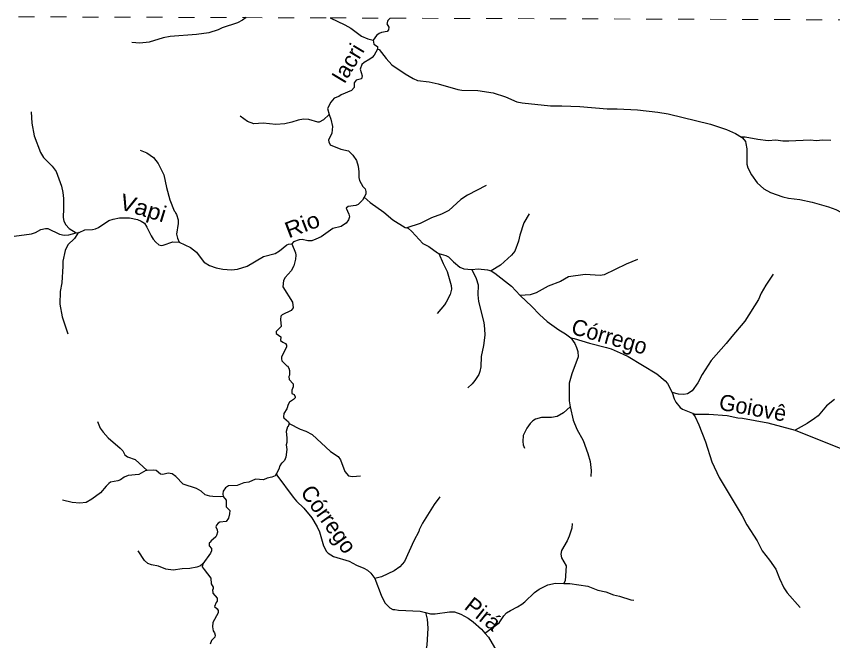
# Model space of a CAD drawing. Extents: x 551.6 to 577.6, y 7567 to 7594.7.
# Drawn here: x 558.55 to 563.65, y 7590.81 to 7594.71 of the extents above; entities that cross this region are included whole.
import ezdxf
from ezdxf.enums import TextEntityAlignment as Align

# ---------------------------------------------------------------- set-up
doc = ezdxf.new("R2010")
doc.units = 0
doc.header["$LTSCALE"] = 0.04
doc.linetypes.add('SHORT_DASHED', pattern=[2.7, 1.5, -1.2])
doc.layers.add('53', color=7, linetype='SHORT_DASHED', lineweight=13)
doc.layers.add('7', color=7, linetype='Continuous', lineweight=25)
doc.layers.add('61', color=7, linetype='Continuous')

msp = doc.modelspace()

# ---------------------------------------------------------------- linework, layer by layer
at = {"layer": '53'}
msp.add_lwpolyline([(557.7663, 7594.7075), (559.9893, 7594.6994), (560.513, 7594.6975), (560.888, 7594.6961), (564.4189, 7594.6832), (564.8007, 7594.6818), (567.5244, 7594.6698), (567.5959, 7594.6695), (570.5848, 7594.6561)], dxfattribs=at)
at = {"layer": '7'}
for points in [[(559.9893, 7594.6994), (559.9657, 7594.6833), (559.9335, 7594.6672), (559.8377, 7594.635), (559.8127, 7594.623), (559.7548, 7594.6053), (559.6791, 7594.594), (559.5134, 7594.5811), (559.4699, 7594.5739), (559.3814, 7594.5465), (559.3234, 7594.5401), (559.2743, 7594.5449)], [(560.513, 7594.6975), (560.6055, 7594.6552), (560.6433, 7594.6326), (560.7093, 7594.5843), (560.7479, 7594.5666), (560.7818, 7594.5593)], [(560.888, 7594.6961), (560.8734, 7594.6809), (560.8678, 7594.6616), (560.8799, 7594.6407), (560.8775, 7594.623), (560.8702, 7594.6133), (560.8332, 7594.606), (560.8187, 7594.5996), (560.8026, 7594.5875), (560.7818, 7594.5593)], [(560.7818, 7594.5593), (560.7865, 7594.5336), (560.8086, 7594.5186), (560.8101, 7594.503)], [(560.8101, 7594.503), (560.7881, 7594.4644), (560.7761, 7594.4507), (560.7616, 7594.4395), (560.7254, 7594.4201), (560.7109, 7594.4057), (560.7012, 7594.3783), (560.7133, 7594.3349), (560.7093, 7594.3171), (560.6762, 7594.3091), (560.6642, 7594.2914), (560.6642, 7594.264), (560.6473, 7594.2439), (560.5829, 7594.2181), (560.5676, 7594.2077), (560.5379, 7594.1956), (560.5177, 7594.1723), (560.4968, 7594.132), (560.5069, 7594.0954)], [(560.8101, 7594.503), (560.82, 7594.501), (560.863, 7594.4435), (560.8984, 7594.4049), (560.9813, 7594.3485), (561.0328, 7594.3187), (561.0586, 7594.3075), (561.131, 7594.2978), (561.1873, 7594.2866), (561.3113, 7594.2495), (561.337, 7594.2463), (561.4352, 7594.2447), (561.5318, 7594.2302), (561.6091, 7594.2045), (561.6799, 7594.1739), (561.7137, 7594.1666), (561.8891, 7594.1481), (561.9616, 7594.1489)], [(561.9616, 7594.1489), (562.0742, 7594.1449), (562.2432, 7594.1288), (562.306, 7594.1296), (562.4332, 7594.124), (562.5603, 7594.1095), (562.6247, 7594.0982), (562.8903, 7594.0338), (562.9901, 7594), (563.0464, 7593.9751), (563.0825, 7593.9534)], [(558.6442, 7594.1119), (558.6482, 7594.0403), (558.6635, 7593.9614), (558.7037, 7593.8568), (558.7214, 7593.8262), (558.7753, 7593.7715), (558.8019, 7593.7377), (558.8341, 7593.6476), (558.8429, 7593.6081), (558.8462, 7593.5703), (558.8478, 7593.5075), (558.8454, 7593.4512), (558.8502, 7593.4287), (558.8614, 7593.4061), (558.8816, 7593.3828), (558.9267, 7593.3549)], [(560.5069, 7594.0954), (560.4727, 7594.0612), (560.4453, 7594.0459), (560.4357, 7594.0459), (560.3793, 7594.0628), (560.3471, 7594.0652), (560.3133, 7594.0596), (560.2731, 7594.0459), (560.2296, 7594.0371), (560.1733, 7594.0322), (560.0944, 7594.0395), (560.0365, 7594.0363), (559.9978, 7594.0499), (559.9504, 7594.0838)], [(560.5069, 7594.0954), (560.5177, 7594.0644), (560.5274, 7594.0186), (560.5233, 7593.9783), (560.5032, 7593.9341), (560.504, 7593.9228), (560.5137, 7593.9051), (560.5805, 7593.8785), (560.6288, 7593.8672), (560.6553, 7593.8407), (560.6779, 7593.8069)], [(563.0825, 7593.9534), (563.0907, 7593.9485), (563.1076, 7593.9258), (563.1116, 7593.9131)], [(563.6412, 7593.9317), (563.5889, 7593.9333), (563.5518, 7593.9308), (563.5116, 7593.9333), (563.3796, 7593.9284), (563.341, 7593.9284), (563.2975, 7593.9333), (563.2492, 7593.9308), (563.1849, 7593.9389), (563.106, 7593.9534), (563.0825, 7593.9534)], [(563.1116, 7593.9131), (563.1172, 7593.8793), (563.1172, 7593.7844), (563.1221, 7593.7618), (563.1454, 7593.7176), (563.1824, 7593.6669), (563.2227, 7593.6298), (563.2637, 7593.6073), (563.3426, 7593.5799), (563.3764, 7593.5719), (563.4472, 7593.5638), (563.5261, 7593.5477), (563.6275, 7593.518), (563.6726, 7593.5003), (563.708, 7593.4818), (563.7192, 7593.4713), (563.7619, 7593.4134)], [(559.3258, 7593.8713), (559.3685, 7593.8552), (559.4087, 7593.8262), (559.4393, 7593.7876), (559.4731, 7593.7184), (559.4908, 7593.6379), (559.5125, 7593.5606), (559.5391, 7593.4922), (559.5455, 7593.4874), (559.5487, 7593.4753), (559.5536, 7593.4705), (559.5632, 7593.4367), (559.564, 7593.4142), (559.5536, 7593.3466), (559.5584, 7593.3224), (559.5693, 7593.2961)], [(560.6779, 7593.8069), (560.6883, 7593.7715), (560.6932, 7593.7361), (560.6932, 7593.7007), (560.6972, 7593.683), (560.7173, 7593.6451), (560.7318, 7593.6299), (560.7366, 7593.6138), (560.7366, 7593.5961), (560.7261, 7593.5775)], [(561.4875, 7593.6516), (561.3708, 7593.5896), (561.3298, 7593.563), (561.2549, 7593.4938), (561.2099, 7593.4721), (561.1471, 7593.4496), (561.0747, 7593.4141), (560.9925, 7593.3862)], [(560.7261, 7593.5775), (560.7157, 7593.559), (560.6892, 7593.5316), (560.6739, 7593.5252), (560.6248, 7593.5204), (560.6143, 7593.5099), (560.6304, 7593.4721), (560.6336, 7593.4544), (560.6288, 7593.4367), (560.6127, 7593.4165), (560.5974, 7593.4045), (560.5821, 7593.3956), (560.5306, 7593.3819), (560.4566, 7593.3312), (560.4244, 7593.3151), (560.3978, 7593.3055), (560.3729, 7593.3047), (560.3375, 7593.3127), (560.3189, 7593.3117), (560.2842, 7593.2987), (560.2738, 7593.2868)], [(560.7261, 7593.5775), (560.7624, 7593.5453), (560.8485, 7593.4842), (560.9057, 7593.4375), (560.9829, 7593.3892), (560.9925, 7593.3862)], [(558.9452, 7593.3578), (558.9806, 7593.3739), (559.0273, 7593.3755), (559.0466, 7593.3803), (559.0651, 7593.3892), (559.1303, 7593.4319), (559.1576, 7593.4415), (559.1979, 7593.4496), (559.259, 7593.4496), (559.3089, 7593.4383), (559.3331, 7593.4286), (559.3524, 7593.4158), (559.3677, 7593.3916)], [(561.7563, 7593.4745), (561.7225, 7593.4174), (561.6976, 7593.3417), (561.6895, 7593.3031), (561.6662, 7593.2411), (561.6461, 7593.2154), (561.5777, 7593.1542), (561.5195, 7593.1171)], [(558.5379, 7593.3353), (558.6474, 7593.3498), (558.6715, 7593.3578), (558.7053, 7593.3755), (558.7343, 7593.382), (558.7496, 7593.382), (558.8228, 7593.3465), (558.8518, 7593.3417), (558.8808, 7593.3433), (558.9267, 7593.3549), (558.9452, 7593.3578)], [(559.3677, 7593.3916), (559.3942, 7593.3369), (559.4079, 7593.316), (559.4232, 7593.2967), (559.4425, 7593.2814), (559.4602, 7593.2765), (559.4699, 7593.2773), (559.5311, 7593.2999), (559.5693, 7593.2961)], [(560.9925, 7593.3862), (561.0006, 7593.3836), (561.0239, 7593.3643), (561.0924, 7593.2894), (561.1294, 7593.2701), (561.1833, 7593.2298), (561.1918, 7593.2272)], [(558.9452, 7593.3578), (558.9355, 7593.349), (558.9162, 7593.3208), (558.8751, 7593.2814), (558.8582, 7593.2452), (558.8421, 7593.1792), (558.8429, 7593.147), (558.8357, 7593.044), (558.826, 7592.9892), (558.8252, 7592.9104), (558.8381, 7592.8315), (558.8743, 7592.7245)], [(559.5693, 7593.2961), (559.6405, 7593.2628), (559.659, 7593.2492), (559.6775, 7593.2339), (559.725, 7593.1695), (559.7323, 7593.1679), (559.7588, 7593.151), (559.8015, 7593.1373), (559.8417, 7593.1293), (559.8964, 7593.1244), (559.9351, 7593.1276), (559.9946, 7593.1478), (560.096, 7593.2065)], [(560.096, 7593.2065), (560.1701, 7593.2266), (560.1974, 7593.2435), (560.2425, 7593.2798), (560.2522, 7593.2854), (560.2738, 7593.2868)], [(560.2738, 7593.2868), (560.2972, 7593.2307), (560.2996, 7593.2162), (560.2972, 7593.1904), (560.2859, 7593.1486), (560.2698, 7593.1172), (560.2328, 7593.0762), (560.2207, 7593.0576), (560.2167, 7593.0182), (560.2779, 7592.9224), (560.2811, 7592.8878), (560.2699, 7592.8709), (560.2143, 7592.8428), (560.2055, 7592.8339), (560.2038, 7592.8138)], [(561.1918, 7593.2272), (561.2187, 7593.1647), (561.2453, 7593.1132), (561.2686, 7593.0263), (561.2718, 7593.0037), (561.2638, 7592.9699), (561.2388, 7592.9216), (561.2284, 7592.9055), (561.1817, 7592.8516)], [(561.1918, 7593.2272), (561.2356, 7593.2138), (561.2533, 7593.2049), (561.2831, 7593.1743), (561.3225, 7593.1413), (561.3483, 7593.1309), (561.3986, 7593.1271)], [(562.434, 7593.1888), (562.3631, 7593.1598), (562.2255, 7593.0938), (562.2014, 7593.0898), (562.1064, 7593.0955), (562.0034, 7593.0802), (561.9519, 7593.052), (561.8746, 7593.0222), (561.8006, 7592.9812), (561.762, 7592.9691), (561.7, 7592.9639)], [(561.3986, 7593.1271), (561.4247, 7593.0697), (561.4376, 7593.0311), (561.4352, 7592.9683), (561.44, 7592.9265), (561.473, 7592.7945), (561.4787, 7592.7558), (561.4803, 7592.7172), (561.4722, 7592.6512), (561.4561, 7592.5836), (561.4545, 7592.5192), (561.4489, 7592.4903), (561.4424, 7592.4709), (561.4175, 7592.4331), (561.4014, 7592.413), (561.3732, 7592.388)], [(561.3986, 7593.1271), (561.4384, 7593.1301), (561.4964, 7593.1252), (561.5195, 7593.1171), (561.543, 7593.1043)], [(561.543, 7593.1043), (561.646, 7593.0214), (561.7, 7592.9639)], [(563.2822, 7593.0963), (563.2363, 7593.0279), (563.2074, 7592.978), (563.1897, 7592.9393), (563.1044, 7592.8033), (563.0223, 7592.7076), (562.9885, 7592.6633), (562.8943, 7592.5587), (562.838, 7592.4709), (562.8106, 7592.4194), (562.776, 7592.3695), (562.7454, 7592.3502), (562.7229, 7592.3454), (562.6891, 7592.347), (562.6504, 7592.3588)], [(561.7, 7592.9639), (561.774, 7592.8943), (561.8215, 7592.8444), (561.8698, 7592.8009), (561.9414, 7592.7502), (561.9841, 7592.7252), (562.0163, 7592.6987)], [(560.2038, 7592.8138), (560.2063, 7592.7695), (560.1749, 7592.7389), (560.1757, 7592.726), (560.2046, 7592.7059), (560.2022, 7592.6834), (560.2167, 7592.6721), (560.2344, 7592.6649), (560.2409, 7592.6544), (560.2401, 7592.6416), (560.2087, 7592.5812), (560.2095, 7592.5691), (560.2119, 7592.5562), (560.2425, 7592.5256), (560.2457, 7592.5256), (560.2545, 7592.5096), (560.2586, 7592.4951), (560.2586, 7592.4661), (560.2554, 7592.4573), (560.257, 7592.4387), (560.2811, 7592.413), (560.2811, 7592.3937), (560.2731, 7592.3736), (560.2747, 7592.3518), (560.2876, 7592.3446), (560.2956, 7592.3309), (560.294, 7592.3245), (560.2844, 7592.314), (560.2594, 7592.2987), (560.2505, 7592.2842), (560.2417, 7592.2553), (560.2248, 7592.2263), (560.2215, 7592.207), (560.2232, 7592.1989), (560.2526, 7592.1755), (560.257, 7592.1636)], [(562.0163, 7592.6987), (562.0412, 7592.6641), (562.0533, 7592.6383), (562.0613, 7592.6142), (562.0629, 7592.5804), (562.0227, 7592.4742), (562.0074, 7592.4162), (562.0058, 7592.3052), (562.0137, 7592.2688)], [(562.0163, 7592.6987), (562.0372, 7592.6955), (562.1338, 7592.6657), (562.24, 7592.6391), (562.2682, 7592.6303), (562.3446, 7592.5973)], [(562.3446, 7592.5973), (562.376, 7592.5836), (562.5547, 7592.475), (562.6062, 7592.4315), (562.6207, 7592.4146), (562.6504, 7592.3588)], [(562.6504, 7592.3588), (562.6633, 7592.318), (562.673, 7592.2987), (562.6996, 7592.2641), (562.7148, 7592.2544), (562.7775, 7592.2296)], [(563.6652, 7592.314), (563.6146, 7592.2746), (563.5623, 7592.2126), (563.5406, 7592.1957), (563.4939, 7592.1651), (563.4193, 7592.1239)], [(562.0137, 7592.2688), (561.9712, 7592.2311), (561.931, 7592.2086), (561.8972, 7592.2021), (561.8344, 7592.2029), (561.7958, 7592.1925), (561.7789, 7592.182), (561.762, 7592.1651), (561.7418, 7592.1353), (561.7201, 7592.0895), (561.7177, 7592.0524), (561.7201, 7592.0307), (561.7266, 7592.0098)], [(562.0137, 7592.2688), (562.0315, 7592.186), (562.0541, 7592.1297), (562.0935, 7592.0589), (562.1241, 7591.9768), (562.137, 7591.9269)], [(562.7775, 7592.2296), (562.7921, 7592.2238), (562.879, 7592.223), (562.9949, 7592.215), (563.0609, 7592.2005), (563.0899, 7592.1973)], [(562.7775, 7592.2296), (562.7937, 7592.2054), (562.8178, 7592.1571), (562.8581, 7592.0508), (562.8975, 7591.9253), (562.9434, 7591.8279), (563.0874, 7591.5873), (563.1164, 7591.5309), (563.1808, 7591.4311), (563.213, 7591.37), (563.2581, 7591.3104)], [(559.0602, 7592.1772), (559.0763, 7592.1361), (559.0956, 7592.1096), (559.1254, 7592.0758), (559.2003, 7592.0114), (559.2172, 7591.9929), (559.23, 7591.9695), (559.2478, 7591.9559), (559.2952, 7591.9389), (559.3702, 7591.871)], [(560.257, 7592.1636), (560.2505, 7592.145), (560.2473, 7592.1434)], [(560.257, 7592.1636), (560.3262, 7592.1281), (560.3616, 7592.1168), (560.401, 7592.0959), (560.5161, 7591.9897), (560.5628, 7591.9591), (560.5789, 7591.9366), (560.6046, 7591.8641), (560.6272, 7591.8384), (560.653, 7591.8343), (560.702, 7591.8368)], [(563.0899, 7592.1973), (563.2476, 7592.1683), (563.4193, 7592.1239)], [(560.2473, 7592.1434), (560.2376, 7592.1136), (560.2425, 7592.075), (560.2425, 7592.046), (560.2393, 7592.0315), (560.2425, 7592.0026), (560.236, 7591.9543), (560.2272, 7591.9333), (560.2119, 7591.9164), (560.2087, 7591.9164), (560.1982, 7591.8995), (560.1926, 7591.8786), (560.1787, 7591.8522)], [(563.4193, 7592.1239), (563.7659, 7591.9824), (563.8569, 7591.9365), (563.922, 7591.8963)], [(562.137, 7591.9269), (562.1442, 7591.8706), (562.1418, 7591.8343)], [(559.3702, 7591.871), (559.362, 7591.8705), (559.317, 7591.8464), (559.251, 7591.84), (559.226, 7591.8287), (559.2027, 7591.8134), (559.1866, 7591.807), (559.1399, 7591.7973), (559.1303, 7591.7901)], [(559.8441, 7591.7094), (559.8281, 7591.7059), (559.7805, 7591.7088), (559.7612, 7591.7104), (559.7323, 7591.7184), (559.7081, 7591.741), (559.6791, 7591.7595), (559.5954, 7591.7853), (559.5495, 7591.8343), (559.5262, 7591.8496), (559.5021, 7591.8544), (559.4683, 7591.8464), (559.4522, 7591.8472), (559.4256, 7591.8705), (559.4119, 7591.8738), (559.3702, 7591.871)], [(560.1787, 7591.8522), (560.1692, 7591.8376), (560.1491, 7591.8295), (560.1202, 7591.823), (560.0976, 7591.8126), (560.0461, 7591.8174), (560.0043, 7591.7989), (559.9737, 7591.7949), (559.9319, 7591.778), (559.8787, 7591.7756), (559.8602, 7591.7635), (559.8457, 7591.7418), (559.8417, 7591.7257), (559.8441, 7591.7094)], [(560.1787, 7591.8522), (560.1802, 7591.8426), (560.2827, 7591.7048), (560.3037, 7591.6798), (560.3487, 7591.6364), (560.3986, 7591.576), (560.4324, 7591.5197), (560.4477, 7591.4875), (560.471, 7591.4006), (560.4904, 7591.3651), (560.5016, 7591.3539), (560.5338, 7591.3345), (560.632, 7591.304), (560.6771, 7591.2798), (560.7238, 7591.2605), (560.7463, 7591.2476), (560.7672, 7591.2299), (560.7924, 7591.1973)], [(559.1303, 7591.7901), (559.1133, 7591.774), (559.0788, 7591.7321), (559.024, 7591.6911), (558.9886, 7591.6718), (558.9484, 7591.6669), (558.9017, 7591.6702), (558.8413, 7591.6863)], [(559.8441, 7591.7094), (559.8626, 7591.6863), (559.8634, 7591.6436), (559.8859, 7591.6211), (559.8851, 7591.6002), (559.8771, 7591.5728), (559.8642, 7591.5518), (559.824, 7591.5478), (559.8135, 7591.5414), (559.8031, 7591.5293), (559.7998, 7591.5189), (559.8071, 7591.5004), (559.8087, 7591.4859), (559.8031, 7591.4641)], [(561.1994, 7591.7056), (561.1624, 7591.6581), (561.0899, 7591.5422), (561.0698, 7591.5004), (561.0682, 7591.4891), (561.036, 7591.4311), (560.9781, 7591.3032), (560.9483, 7591.2686), (560.9137, 7591.2436), (560.8348, 7591.2074), (560.7924, 7591.1973)], [(562.0259, 7591.5398), (562.0227, 7591.5116), (562.0074, 7591.4601), (561.9937, 7591.4311), (561.9583, 7591.3716), (561.9551, 7591.3491), (561.9583, 7591.3265), (561.9873, 7591.2758), (561.9825, 7591.1816), (561.9792, 7591.1808), (561.9727, 7591.1662)], [(559.8031, 7591.4641), (559.7998, 7591.4561), (559.7676, 7591.4295), (559.7668, 7591.4247), (559.758, 7591.4175), (559.758, 7591.4006), (559.7709, 7591.3829), (559.7709, 7591.3684), (559.7652, 7591.3539), (559.7186, 7591.2878)], [(559.7186, 7591.2878), (559.7025, 7591.2758), (559.6808, 7591.2677), (559.6373, 7591.2589), (559.589, 7591.2573), (559.5327, 7591.2476), (559.486, 7591.2541), (559.4409, 7591.2726), (559.3959, 7591.2822), (559.3733, 7591.2911), (559.354, 7591.3088), (559.3146, 7591.3692)], [(559.7186, 7591.2878), (559.7145, 7591.2702), (559.725, 7591.2525), (559.7684, 7591.1994), (559.7701, 7591.1623), (559.7829, 7591.143), (559.7813, 7591.1293), (559.7789, 7591.1285), (559.7805, 7591.1052), (559.8071, 7591.073), (559.8079, 7591.0545), (559.8014, 7591.0472), (559.791, 7591.0223), (559.8079, 7591.007), (559.8143, 7590.9966), (559.8143, 7590.9821), (559.7805, 7590.9209), (559.7773, 7590.8951), (559.7821, 7590.8686), (559.7902, 7590.8581), (559.7942, 7590.842), (559.7918, 7590.8308), (559.7725, 7590.8098), (559.7628, 7590.7857)], [(563.2581, 7591.3104), (563.2975, 7591.2541), (563.32, 7591.1961), (563.349, 7591.1382), (563.3683, 7591.1068), (563.4496, 7591.0151)], [(560.7924, 7591.1973), (560.8316, 7591.0915), (560.8549, 7591.0448), (560.8871, 7591.0142), (560.9057, 7591.0038), (560.9169, 7591.0022)], [(561.4806, 7590.8554), (561.5688, 7590.9201), (561.5994, 7590.9635), (561.6155, 7590.9812), (561.6396, 7590.9973), (561.6847, 7591.0191), (561.7104, 7591.0352), (561.7306, 7591.0504), (561.7893, 7591.1092), (561.8199, 7591.1293), (561.873, 7591.1559), (561.9213, 7591.1671), (561.9727, 7591.1662)], [(561.9727, 7591.1662), (562.0115, 7591.1655), (562.1241, 7591.1494), (562.1861, 7591.1245)], [(562.1861, 7591.1245), (562.2368, 7591.1124), (562.2835, 7591.0947), (562.3221, 7591.0859), (562.3929, 7591.0625), (562.4098, 7591.0609)], [(560.9169, 7591.0022), (560.9395, 7590.9981), (561.0747, 7590.9925), (561.1096, 7590.9836)], [(561.1096, 7590.9836), (561.1189, 7590.9434), (561.1245, 7590.8855), (561.1173, 7590.7793), (561.102, 7590.7117), (561.0771, 7590.6408), (561.0602, 7590.6022), (561.0296, 7590.5024), (561.0207, 7590.4541), (561.0215, 7590.4348), (561.0127, 7590.3704), (561.0135, 7590.3302), (561.0207, 7590.3068)], [(561.1096, 7590.9836), (561.1407, 7590.9756), (561.1696, 7590.9756), (561.2598, 7590.9885), (561.2911, 7590.9885), (561.3298, 7590.974), (561.3765, 7590.9482), (561.4078, 7590.9249), (561.4593, 7590.879), (561.4806, 7590.8554)], [(561.4806, 7590.8554), (561.5028, 7590.8308), (561.5543, 7590.7406), (561.6259, 7590.5974), (561.6726, 7590.5185), (561.7233, 7590.471), (561.7797, 7590.4372)]]:
    msp.add_lwpolyline(points, dxfattribs=at)

# ---------------------------------------------------------------- texts
at = {"layer": '61'}
for s, rotation, p in [('Iacri', 58.944, (560.6669, 7594.389)), ('Córrego', 344.048, (562.245, 7592.66)), ('Goiovê', 349.668, (563.1456, 7592.214)), ('Córrego', 305.426, (560.4631, 7591.5381)), ('Pirá', 321.358, (561.4374, 7590.9364))]:
    msp.add_text(s, height=0.1, rotation=rotation, dxfattribs=at).set_placement(p, align=Align.CENTER)
at = {"layer": '61', "width": 1.1}
for s, rotation, p in [('Vapi', 342.869, (559.3302, 7593.4629)), ('Rio', 21.032, (560.3569, 7593.3596))]:
    msp.add_text(s, height=0.1, rotation=rotation, dxfattribs=at).set_placement(p, align=Align.CENTER)

doc.saveas('drawing.dxf')
